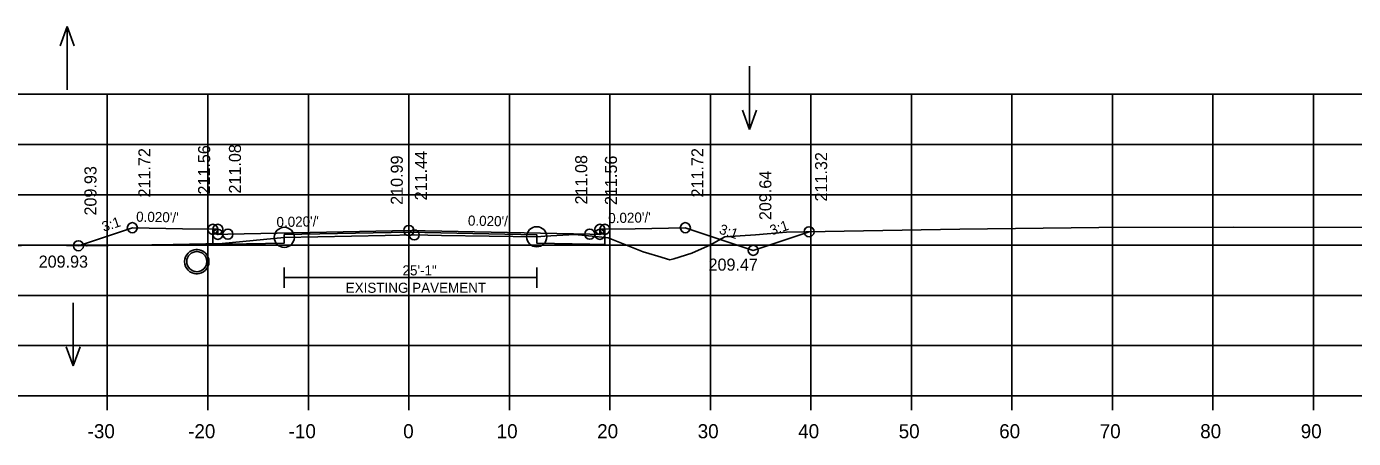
# Model space of a CAD drawing. Extents: x 1368968 to 1369915, y 377395 to 380381.
# Drawn here: x 1369100.1 to 1369232.1, y 378788.5 to 378829.4 of the extents above; entities that cross this region are included whole.
import ezdxf

# ---------------------------------------------------------------- set-up
doc = ezdxf.new("R2010")
doc.units = 0
for name, color, linetype in [('S_BORDER_NO_PLOT', 7, 'Continuous'), ('S_BREAKLINE_ANNOT', 7, 'Continuous'), ('S_BRIDGE', 7, 'Continuous'), ('S_CROSS_DRAIN', 7, 'Continuous'), ('S_CTL_TABLE', 7, 'Continuous'), ('S_CURB_ANNOT', 7, 'Continuous'), ('S_DITCHLINE_ANNOT', 7, 'Continuous'), ('S_DROP_INLET', 7, 'Continuous'), ('S_EXIST_ROW_ANNOT', 7, 'Continuous'), ('S_EXISTING_ALIGNMENT', 7, 'Continuous'), ('S_EXISTING_ALIGNMENT_ANNOT', 7, 'Continuous'), ('S_FENCE', 7, 'Continuous')]:
    doc.layers.add(name, color=color, linetype=linetype)

msp = doc.modelspace()

# ---------------------------------------------------------------- linework, layer by layer
at = {"layer": 'S_BORDER_NO_PLOT'}
msp.add_lwpolyline([(1369118.62, 378809.26), (1369118.63, 378807.75), (1369120.13, 378807.78), (1369125.74, 378807.89), (1369125.74, 378808.73), (1369138.13, 378808.97), (1369150.85, 378808.72), (1369150.85, 378807.89), (1369156.13, 378807.78), (1369157.63, 378807.75), (1369157.64, 378809.26)], dxfattribs=at)
at = {"layer": 'S_BREAKLINE_ANNOT'}
for p, q in [((1368998.13, 378792.7), (1369278.13, 378792.7)), ((1369108.13, 378791.3), (1369108.13, 378792.7)), ((1369118.13, 378791.3), (1369118.13, 378792.7)), ((1369128.13, 378791.3), (1369128.13, 378792.7)), ((1369138.13, 378791.3), (1369138.13, 378792.7)), ((1369148.13, 378791.3), (1369148.13, 378792.7)), ((1369158.13, 378791.3), (1369158.13, 378792.7)), ((1369168.13, 378791.3), (1369168.13, 378792.7)), ((1369178.13, 378791.3), (1369178.13, 378792.7)), ((1369188.13, 378791.3), (1369188.13, 378792.7)), ((1369198.13, 378791.3), (1369198.13, 378792.7)), ((1369208.13, 378791.3), (1369208.13, 378792.7)), ((1369218.13, 378791.3), (1369218.13, 378792.7)), ((1369228.13, 378791.3), (1369228.13, 378792.7))]:
    msp.add_line(p, q, dxfattribs=at)
at = {"layer": 'S_CROSS_DRAIN'}
msp.add_line((1369125.74, 378804.46), (1369150.85, 378804.46), dxfattribs=at)
at = {"layer": 'S_CTL_TABLE'}
msp.add_lwpolyline([(1369094.68, 378807.57), (1369102.03, 378807.68), (1369106.06, 378807.62), (1369106.07, 378807.62), (1369106.14, 378807.62), (1369114.67, 378807.74), (1369119.54, 378807.85), (1369125.74, 378808.46), (1369135.78, 378808.65), (1369138.67, 378808.7), (1369141.38, 378808.66), (1369150.85, 378808.52), (1369151.67, 378808.57), (1369154.65, 378808.73), (1369156.69, 378808.55), (1369157.95, 378808.4), (1369161.46, 378807.03), (1369162.02, 378806.85), (1369162.9, 378806.6), (1369164.11, 378806.24), (1369164.49, 378806.34), (1369166.29, 378806.88), (1369168.13, 378807.73), (1369169.58, 378808.52), (1369172.61, 378808.72), (1369175.69, 378808.99), (1369192.94, 378809.27), (1369206.77, 378809.43), (1369220.17, 378809.47), (1369254.1, 378809.4)], dxfattribs=at)
at = {"layer": 'S_CURB_ANNOT'}
msp.add_lwpolyline([(1369105.25, 378807.63), (1369110.62, 378809.42), (1369115.62, 378809.32), (1369118.62, 378809.26), (1369119.12, 378809.26), (1369119.13, 378808.76), (1369120.13, 378808.78), (1369138.13, 378809.14), (1369156.13, 378808.78), (1369157.13, 378808.76), (1369157.14, 378809.26), (1369157.64, 378809.26), (1369160.64, 378809.32), (1369165.64, 378809.42), (1369172.4, 378807.17), (1369177.95, 378809.02)], dxfattribs=at)
at = {"layer": 'S_DITCHLINE_ANNOT'}
for p, q in [((1368998.13, 378822.7), (1369278.13, 378822.7)), ((1369108.13, 378792.7), (1369108.13, 378822.7)), ((1369118.13, 378792.7), (1369118.13, 378822.7)), ((1369128.13, 378792.7), (1369128.13, 378822.7)), ((1369138.13, 378792.7), (1369138.13, 378822.7)), ((1369148.13, 378792.7), (1369148.13, 378822.7)), ((1369158.13, 378792.7), (1369158.13, 378822.7)), ((1369168.13, 378792.7), (1369168.13, 378822.7)), ((1369178.13, 378792.7), (1369178.13, 378822.7)), ((1369188.13, 378792.7), (1369188.13, 378822.7)), ((1369198.13, 378792.7), (1369198.13, 378822.7)), ((1369208.13, 378792.7), (1369208.13, 378822.7)), ((1369218.13, 378792.7), (1369218.13, 378822.7)), ((1369228.13, 378792.7), (1369228.13, 378822.7)), ((1368998.13, 378817.7), (1369278.13, 378817.7)), ((1368998.13, 378812.7), (1369278.13, 378812.7)), ((1368998.13, 378807.7), (1369278.13, 378807.7)), ((1368998.13, 378802.7), (1369278.13, 378802.7)), ((1368998.13, 378797.7), (1369278.13, 378797.7)), ((1368998.13, 378792.7), (1369278.13, 378792.7))]:
    msp.add_line(p, q, dxfattribs=at)
at = {"layer": 'S_DROP_INLET'}
for p, q in [((1369116.95, 378807.27), (1369117.11, 378807.26)), ((1369116.95, 378804.85), (1369117.11, 378804.84))]:
    msp.add_line(p, q, dxfattribs=at)
for centre, radius in [((1369110.62, 378809.42), 0.5), ((1369118.62, 378809.26), 0.5), ((1369119.12, 378809.26), 0.5), ((1369125.74, 378808.46), 1), ((1369138.13, 378809.14), 0.5), ((1369150.85, 378808.52), 1), ((1369157.14, 378809.26), 0.5), ((1369157.64, 378809.26), 0.5), ((1369165.64, 378809.42), 0.5), ((1369177.95, 378809.02), 0.5), ((1369105.25, 378807.63), 0.5), ((1369119.13, 378808.76), 0.5), ((1369120.13, 378808.78), 0.5), ((1369120.13, 378808.78), 0.5), ((1369138.67, 378808.7), 0.5), ((1369156.13, 378808.78), 0.5), ((1369156.13, 378808.78), 0.5), ((1369157.13, 378808.76), 0.5), ((1369117.03, 378806.05), 1.21), ((1369172.4, 378807.17), 0.5)]:
    msp.add_circle(centre, radius, dxfattribs=at)
at = {"layer": 'S_EXIST_ROW_ANNOT'}
for p, q in [((1369116.95, 378807.06), (1369117.11, 378807.05)), ((1369125.74, 378803.46), (1369125.74, 378805.46)), ((1369150.85, 378803.46), (1369150.85, 378805.46)), ((1369116.95, 378805.06), (1369117.11, 378805.05))]:
    msp.add_line(p, q, dxfattribs=at)
msp.add_circle((1369117.03, 378806.05), 1, dxfattribs=at)
at = {"layer": 'S_EXISTING_ALIGNMENT'}
for p, q in [((1369104.14, 378829.4), (1369103.44, 378827.48)), ((1369104.14, 378823.12), (1369104.14, 378829.4)), ((1369104.14, 378829.4), (1369104.84, 378827.48)), ((1369172.03, 378825.46), (1369172.03, 378819.17)), ((1369172.03, 378819.17), (1369171.33, 378821.1)), ((1369172.03, 378819.17), (1369172.73, 378821.1)), ((1369104.72, 378801.97), (1369104.72, 378795.68)), ((1369104.72, 378795.68), (1369104.02, 378797.6)), ((1369104.72, 378795.68), (1369105.42, 378797.6))]:
    msp.add_line(p, q, dxfattribs=at)
at = {"layer": 'S_EXISTING_ALIGNMENT_ANNOT'}
msp.add_line((1369138.13, 378808.69), (1369138.13, 378818.69), dxfattribs=at)

# ---------------------------------------------------------------- texts
at = {"layer": 'S_BRIDGE'}
for s, p in [('-30', (1369106.17, 378788.5)), ('-20', (1369116.17, 378788.5)), ('-10', (1369126.17, 378788.5)), ('0', (1369137.57, 378788.5)), ('10', (1369146.87, 378788.5)), ('20', (1369156.87, 378788.5)), ('30', (1369166.87, 378788.5)), ('40', (1369176.87, 378788.5)), ('50', (1369186.87, 378788.5)), ('60', (1369196.87, 378788.5)), ('70', (1369206.87, 378788.5)), ('80', (1369216.87, 378788.5)), ('90', (1369226.87, 378788.5))]:
    msp.add_text(s, height=1.4, dxfattribs=at).set_placement(p)
at = {"layer": 'S_EXIST_ROW_ANNOT'}
for s, height, p in [('209.93', 1.2, (1369101.3, 378805.45)), ('25\'-1"', 1, (1369137.5, 378804.68)), ('209.47', 1.2, (1369167.95, 378805.15)), ('EXISTING PAVEMENT', 1, (1369131.85, 378802.95))]:
    msp.add_text(s, height=height, dxfattribs=at).set_placement(p)
at = {"layer": 'S_EXISTING_ALIGNMENT_ANNOT'}
for s, p in [('211.56', (1369118.36, 378812.71)), ('211.08', (1369121.43, 378812.81)), ('211.72', (1369112.42, 378812.42)), ('210.99', (1369137.53, 378811.69)), ('211.44', (1369139.93, 378812.14)), ('211.08', (1369155.88, 378811.73)), ('211.56', (1369158.84, 378811.67)), ('211.72', (1369167.44, 378812.42)), ('211.32', (1369179.75, 378812.02)), ('209.93', (1369107.05, 378810.63)), ('209.64', (1369174.2, 378810.17))]:
    msp.add_text(s, height=1.2, rotation=90, dxfattribs=at).set_placement(p)
at = {"layer": 'S_FENCE'}
for s, rotation, p in [("0.020'/'", 358.8541, (1369110.99, 378810.02)), ("0.020'/'", 1.1459, (1369157.98, 378809.87)), ('3:1', 18.4324, (1369107.78, 378809)), ("0.020'/'", 1.1457, (1369124.97, 378809.48)), ("0.020'/'", 358.8542, (1369144, 378809.63)), ('3:1', 341.5676, (1369168.93, 378808.86)), ('3:1', 18.4253, (1369174.24, 378808.65))]:
    msp.add_text(s, height=1, rotation=rotation, dxfattribs=at).set_placement(p)

doc.saveas('drawing.dxf')
